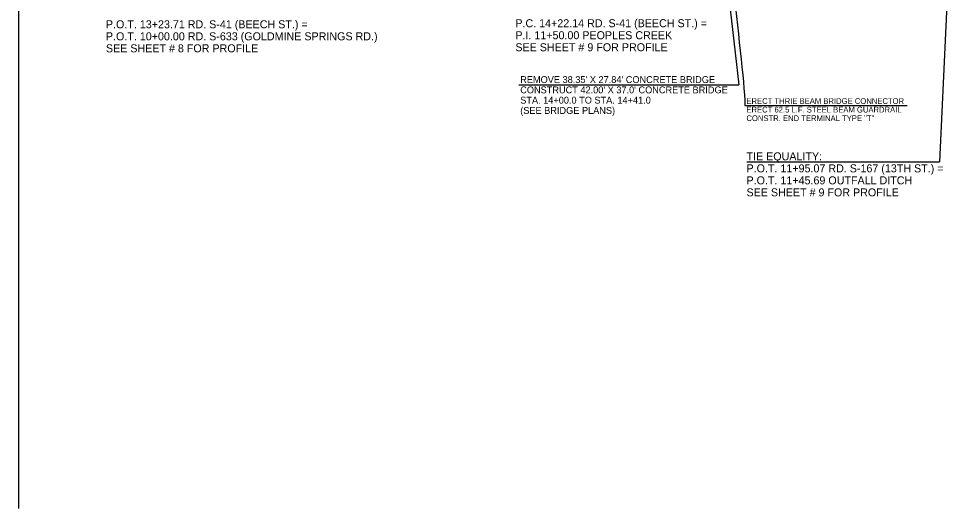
# Model space of a CAD drawing. Extents: x 16382402 to 16388022, y 46194326 to 46202918.
# Drawn here: x 16384351 to 16385166, y 46194371 to 46194799 of the extents above; entities that cross this region are included whole.
import ezdxf

# ---------------------------------------------------------------- set-up
doc = ezdxf.new("R2010")
doc.units = 0
for name, color, linetype in [('RD_EX_Bridge', 7, 'Continuous'), ('RD_GPK_Profile_Cell', 7, 'Continuous'), ('RD_HC_Data', 7, 'Continuous'), ('RD_PD_ALT2_TX', 7, 'Continuous')]:
    doc.layers.add(name, color=color, linetype=linetype)

msp = doc.modelspace()

# ---------------------------------------------------------------- linework, layer by layer
at = {"layer": 'RD_EX_Bridge'}
for p in [(16384951.1, 46195001.3), (16384788.65, 46194741.12)]:
    msp.add_line(p, (16384980.81, 46194741.12), dxfattribs=at)
at = {"layer": 'RD_GPK_Profile_Cell'}
msp.add_line((16384351.35, 46195620.8), (16384351.35, 46194370.8), dxfattribs=at)
at = {"layer": 'RD_HC_Data'}
for p in [(16385165.83, 46194878.95), (16384987.92, 46194673.58)]:
    msp.add_line(p, (16385156.24, 46194673.58), dxfattribs=at)
at = {"layer": 'RD_PD_ALT2_TX'}
msp.add_line((16384986.24, 46194723.05), (16385128.16, 46194723.05), dxfattribs=at)
msp.add_open_spline([(16384979.58, 46194986.31), (16384971.13, 46194970.09), (16384968.98, 46194945.44), (16384967.21, 46194921.07), (16384973.36, 46194841.3), (16384985.67, 46194744.46), (16384986.24, 46194723.05)], degree=3, dxfattribs=at)

# ---------------------------------------------------------------- texts
at = {"layer": 'RD_EX_Bridge'}
for s, p in [("REMOVE 38.35' X 27.84' CONCRETE BRIDGE", (16384789.82, 46194742.6)), ("CONSTRUCT 42.00' X 37.0' CONCRETE BRIDGE ", (16384789.82, 46194733.6)), ('STA. 14+00.0 TO STA. 14+41.0 ', (16384789.82, 46194724.6)), ('(SEE BRIDGE PLANS)', (16384789.82, 46194715.6))]:
    msp.add_text(s, height=6, dxfattribs=at).set_placement(p)
at = {"layer": 'RD_HC_Data'}
for s, p in [('P.O.T. 13+23.71 RD. S-41 (BEECH ST.) =', (16384427.64, 46194790.43)), ('P.C. 14+22.14 RD. S-41 (BEECH ST.) =', (16384785.56, 46194791.36)), ('P.O.T. 10+00.00 RD. S-633 (GOLDMINE SPRINGS RD.)', (16384427.64, 46194779.93)), ('P.I. 11+50.00 PEOPLES CREEK', (16384785.56, 46194780.86)), ('SEE SHEET # 8 FOR PROFILE', (16384427.64, 46194769.43)), ('SEE SHEET # 9 FOR PROFILE', (16384785.56, 46194770.36)), ('TIE EQUALITY:', (16384987.62, 46194675.01)), ('P.O.T. 11+95.07 RD. S-167 (13TH ST.) =', (16384987.62, 46194664.51)), ('P.O.T. 11+45.69 OUTFALL DITCH', (16384987.62, 46194654.01)), ('SEE SHEET # 9 FOR PROFILE', (16384987.62, 46194643.51))]:
    msp.add_text(s, height=7, dxfattribs=at).set_placement(p)
at = {"layer": 'RD_PD_ALT2_TX'}
for s, p in [('ERECT THRIE BEAM BRIDGE CONNECTOR', (16384987.55, 46194724.33)), ('ERECT 62.5 L.F. STEEL BEAM GUARDRAIL', (16384987.55, 46194716.83)), ('CONSTR. END TERMINAL TYPE "T"', (16384987.55, 46194709.33))]:
    msp.add_text(s, height=5, dxfattribs=at).set_placement(p)

doc.saveas('drawing.dxf')
